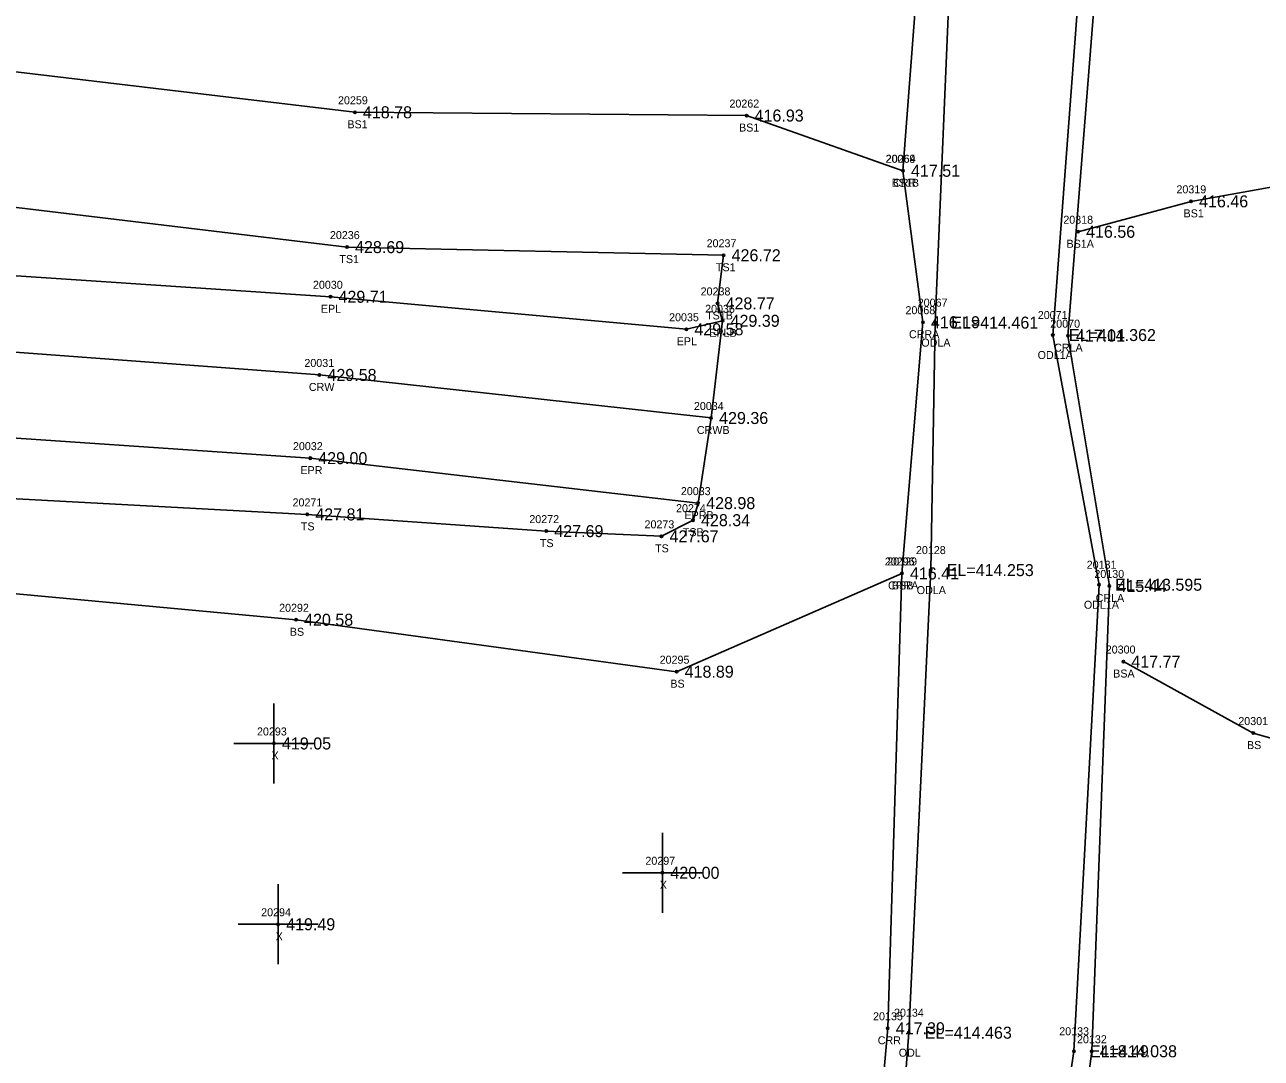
# Model space of a CAD drawing. Extents: x 1613184 to 1614731, y 770859 to 771868.
# Drawn here: x 1613805.1 to 1613959.6, y 771266.5 to 771395.6 of the extents above; entities that cross this region are included whole.
import ezdxf

# ---------------------------------------------------------------- set-up
doc = ezdxf.new("R2010")
doc.units = 0
for name, color, linetype in [('RD_DTM_BkLn1', 7, 'Continuous'), ('RD_DTM_BkLn2', 7, 'Continuous'), ('RD_DTM_BkLn_txCode', 7, 'Continuous'), ('RD_EX_H2O', 7, 'Continuous'), ('RD_EX_H2O_txCode', 7, 'Continuous'), ('RD_EX_Misc', 7, 'Continuous'), ('RD_EX_Misc_txCode', 7, 'Continuous'), ('RD_EX_Road', 7, 'Continuous'), ('RD_EX_Road_txCode', 7, 'Continuous'), ('RD_EX_TX_H2O_ELEV', 7, 'Continuous'), ('RD_EX_TX_Misc_ELEV', 7, 'Continuous'), ('RD_EX_TX_Road_ELEV', 7, 'Continuous'), ('RD_HC_Survey_ELEV', 7, 'Continuous'), ('RD_HC_Survey_txCode', 7, 'Continuous'), ('RD_SMD_Locator', 7, 'Continuous')]:
    doc.layers.add(name, color=color, linetype=linetype)

msp = doc.modelspace()

# ---------------------------------------------------------------- linework, layer by layer
at = {"layer": 'RD_DTM_BkLn1'}
msp.add_lwpolyline([(1613193.64, 771319.41), (1613293.11, 771329.14), (1613392.46, 771338.5), (1613492.95, 771347.08), (1613542.61, 771350.97), (1613592.52, 771354.09), (1613642.63, 771355.86), (1613692.27, 771356.69), (1613742.08, 771356.79), (1613792.13, 771355.6), (1613841.94, 771351.86), (1613890.87, 771346.48)], dxfattribs=at)
at = {"layer": 'RD_DTM_BkLn2'}
for points in [[(1613191.9, 771337.48), (1613291.44, 771345.53), (1613389.08, 771355.5), (1613435.73, 771361.94), (1613448.05, 771379.9), (1613456.58, 771373.81), (1613489.82, 771379.95), (1613539.65, 771385.9), (1613590.16, 771390.66), (1613642.18, 771393.2), (1613691.23, 771395.53), (1613743.12, 771392.35), (1613794.87, 771390.82), (1613846.37, 771384.69), (1613895.3, 771384.28), (1613914.84, 771377.38)], [(1613936.71, 771369.76), (1613950.83, 771373.56), (1613963.82, 771375.88), (1614069.43, 771354.05), (1614168.59, 771333.61), (1614242.69, 771319.53), (1614249.02, 771318.73)], [(1613192.28, 771333.37), (1613291.74, 771342.64), (1613389.11, 771353.66), (1613436.85, 771356.33), (1613492.16, 771363.71), (1613540.47, 771367.11), (1613591.24, 771372.7), (1613642.11, 771373.16), (1613691.12, 771373.65), (1613744.36, 771374.73), (1613793.64, 771374.02), (1613845.39, 771367.84), (1613892.43, 771366.82), (1613891.67, 771360.8)], [(1613888.61, 771333.71), (1613889.25, 771335.84), (1613890.87, 771346.48), (1613892.3, 771358.63), (1613891.67, 771360.8)], [(1613513, 771333.25), (1613544.25, 771334.4), (1613593.37, 771335.17), (1613642.92, 771335.51), (1613693.05, 771337.53), (1613742.72, 771338.4), (1613791.72, 771337.06), (1613840.42, 771334.43), (1613870.28, 771332.34), (1613884.67, 771331.69), (1613888.61, 771333.71)], [(1613531.71, 771317.92), (1613595.86, 771321.39), (1613644.57, 771324.66), (1613693.19, 771325.79), (1613742.08, 771324.98), (1613790.16, 771325.78), (1613839.02, 771321.26), (1613886.56, 771314.77), (1613914.71, 771327.05)], [(1613942.37, 771316.04), (1613958.6, 771307.1), (1613993.85, 771297.11), (1614061.98, 771289.14), (1614161.12, 771278.24), (1614255.97, 771263.05), (1614304.44, 771258.76), (1614327.58, 771260.25), (1614357.86, 771257.94), (1614459.3, 771244.57), (1614558.63, 771228.44), (1614632.25, 771215.15), (1614636.04, 771209.87), (1614639.16, 771208.8), (1614642.36, 771211.01), (1614643.75, 771203.68), (1614650.35, 771198.32), (1614658.52, 771198.65)]]:
    msp.add_lwpolyline(points, dxfattribs=at)
at = {"layer": 'RD_EX_H2O'}
for p, q in [((1613917.33, 771358.45), (1613914.71, 771327.05)), ((1613918.3, 771327.47), (1613918.86, 771358.4)), ((1613933.56, 771356.85), (1613939.34, 771325.64)), ((1613940.63, 771325.49), (1613935.44, 771356.77))]:
    msp.add_line(p, q, dxfattribs=at)
for points in [[(1613935.44, 771356.77), (1613943.27, 771455.38), (1613930.01, 771555.13), (1613904.31, 771653.52), (1613890.61, 771671.71), (1613879.59, 771707.51), (1613867.74, 771752.9), (1613852.65, 771773.53), (1613849.08, 771793.99), (1613835.96, 771848.52)], [(1613933.56, 771356.85), (1613941.09, 771457.11), (1613927.24, 771554.95), (1613896.69, 771649.06), (1613889.05, 771670.7), (1613877.65, 771707.88), (1613864.46, 771751.42), (1613851.59, 771772.54), (1613846.49, 771794.39), (1613833.03, 771846.8)], [(1613917.33, 771358.45), (1613914.84, 771377.38), (1613920.97, 771458.1), (1613902.34, 771553.43), (1613877.06, 771642.7), (1613869.36, 771660.93), (1613852.51, 771699.26), (1613841.87, 771743.26), (1613831.92, 771763.8), (1613826.06, 771789.11), (1613812.2, 771844.94)], [(1613918.86, 771358.4), (1613923.07, 771457.63), (1613904.68, 771553.56), (1613879.07, 771643.9), (1613870.63, 771662.43), (1613861.21, 771701.73), (1613845.61, 771745.37), (1613835.05, 771764.94), (1613829.4, 771789.26), (1613813.84, 771845.46)], [(1613914.71, 771327.05), (1613912.94, 771270.2), (1613909.29, 771229.14), (1613936.32, 771173.24), (1613961.59, 771155.78), (1613976.99, 771153.11), (1613987.89, 771138.66), (1614016.07, 771061.15), (1614064.07, 770971.34), (1614114.62, 770881.02)], [(1613918.3, 771327.47), (1613915.56, 771269.65), (1613912.54, 771229.9), (1613937.35, 771175.56), (1613962.55, 771156.92), (1613978.15, 771155.33), (1613989.65, 771139.95), (1614019.92, 771062.64), (1614066.64, 770972.38), (1614116.22, 770882.03)], [(1613939.34, 771325.64), (1613936.19, 771267.33), (1613931.54, 771235.48), (1613951.01, 771188.77), (1613971.87, 771179.88), (1613985.53, 771176.18), (1614010.21, 771154.12), (1614036.29, 771069.78), (1614094.78, 770976.9), (1614137.18, 770892.4)], [(1613940.63, 771325.49), (1613938.42, 771267.33), (1613934.3, 771235.92), (1613956.7, 771194.52), (1613973.34, 771185.91), (1613987.6, 771179.19), (1614011.07, 771155.33), (1614038.76, 771071.93), (1614097.41, 770977.46), (1614139.24, 770893.98)]]:
    msp.add_lwpolyline(points, dxfattribs=at)
at = {"layer": 'RD_EX_Misc'}
for p, q in [((1613836.26, 771300.8), (1613836.26, 771310.8)), ((1613831.26, 771305.8), (1613841.26, 771305.8)), ((1613884.78, 771284.64), (1613884.78, 771294.64)), ((1613879.78, 771289.64), (1613889.78, 771289.64)), ((1613836.78, 771278.2), (1613836.78, 771288.2)), ((1613831.78, 771283.2), (1613841.78, 771283.2))]:
    msp.add_line(p, q, dxfattribs=at)
at = {"layer": 'RD_EX_Road'}
for points in [[(1613192.48, 771329.15), (1613292.05, 771338.23), (1613391, 771348.45), (1613492.61, 771357.17), (1613541.86, 771361.21), (1613591.56, 771364.71), (1613642.92, 771366.4), (1613692.81, 771367.35), (1613742.66, 771367.02), (1613792.19, 771365.04), (1613843.32, 771361.63), (1613887.78, 771357.57), (1613892.3, 771358.63)], [(1613194.6, 771309.27), (1613294.55, 771318.15), (1613393.75, 771328.31), (1613493.74, 771336.74), (1613544.27, 771340.57), (1613593.48, 771343.76), (1613642.77, 771345.54), (1613692.58, 771346.11), (1613741.71, 771345.82), (1613791.79, 771344.79), (1613840.79, 771341.46), (1613889.25, 771335.84)]]:
    msp.add_lwpolyline(points, dxfattribs=at)
at = {"layer": 'RD_SMD_Locator'}
for centre in [(1613846.37, 771384.69), (1613895.3, 771384.28), (1613914.84, 771377.38), (1613914.84, 771377.38), (1613950.83, 771373.56), (1613936.71, 771369.76), (1613845.39, 771367.84), (1613892.43, 771366.82), (1613843.32, 771361.63), (1613891.67, 771360.8), (1613892.3, 771358.63), (1613917.33, 771358.45), (1613918.86, 771358.4), (1613887.78, 771357.57), (1613933.56, 771356.85), (1613935.44, 771356.77), (1613841.94, 771351.86), (1613890.87, 771346.48), (1613840.79, 771341.46), (1613889.25, 771335.84), (1613840.42, 771334.43), (1613888.61, 771333.71), (1613870.28, 771332.34), (1613884.67, 771331.69), (1613914.71, 771327.05), (1613914.71, 771327.05), (1613918.3, 771327.47), (1613939.34, 771325.64), (1613940.63, 771325.49), (1613839.02, 771321.26), (1613942.37, 771316.04), (1613886.56, 771314.77), (1613958.6, 771307.1), (1613836.26, 771305.8), (1613884.78, 771289.64), (1613836.78, 771283.2), (1613912.94, 771270.2), (1613915.56, 771269.65), (1613936.19, 771267.33), (1613938.42, 771267.33)]:
    msp.add_circle(centre, 0.15, dxfattribs=at)

# ---------------------------------------------------------------- texts
at = {"layer": 'RD_DTM_BkLn_txCode'}
for s, p in [('20259', (1613844.26, 771385.69)), ('20262', (1613893.16, 771385.28)), ('BS1', (1613845.43, 771382.69)), ('BS1', (1613894.36, 771382.28)), ('20264', (1613912.7, 771378.38)), ('BS1B', (1613913.42, 771375.38)), ('20319', (1613949, 771374.56)), ('20318', (1613934.87, 771370.76)), ('BS1', (1613949.89, 771371.56)), ('20236', (1613843.25, 771368.84)), ('20237', (1613890.31, 771367.82)), ('BS1A', (1613935.27, 771367.76)), ('TS1', (1613844.43, 771365.84)), ('TS1', (1613891.47, 771364.82)), ('20238', (1613889.56, 771361.8)), ('TS1B', (1613890.24, 771358.8)), ('20271', (1613838.58, 771335.43)), ('20274', (1613886.49, 771334.71)), ('TS', (1613839.62, 771332.43)), ('20272', (1613868.16, 771333.34)), ('20273', (1613882.55, 771332.69)), ('TSB', (1613887.34, 771331.71)), ('TS', (1613869.48, 771330.34)), ('TS', (1613883.87, 771329.69)), ('20296', (1613912.57, 771328.05)), ('BSB', (1613913.46, 771325.05)), ('20292', (1613836.9, 771322.26)), ('BS', (1613838.24, 771319.26)), ('20300', (1613940.17, 771317.04)), ('20295', (1613884.44, 771315.77)), ('BSA', (1613941.1, 771314.04)), ('BS', (1613885.78, 771312.77)), ('20301', (1613956.73, 771308.1)), ('BS', (1613957.82, 771305.1))]:
    msp.add_text(s, height=1, dxfattribs=at).set_placement(p)
at = {"layer": 'RD_EX_H2O_txCode'}
for s, p in [('20069', (1613912.66, 771378.38)), ('CRR', (1613913.59, 771375.38)), ('20067', (1613916.68, 771360.4)), ('20068', (1613915.15, 771359.45)), ('20071', (1613931.68, 771358.85)), ('20070', (1613933.24, 771357.77)), ('CRRA', (1613915.59, 771356.45)), ('ODLA', (1613917.13, 771355.4)), ('ODL1A', (1613931.66, 771353.85)), ('CRLA', (1613933.72, 771354.77)), ('20128', (1613916.46, 771329.47)), ('20129', (1613912.88, 771328.05)), ('20131', (1613937.79, 771327.64)), ('20130', (1613938.75, 771326.49)), ('CRRA', (1613912.97, 771325.05)), ('ODLA', (1613916.56, 771324.47)), ('CRLA', (1613938.91, 771323.49)), ('ODL1A', (1613937.44, 771322.64)), ('20135', (1613911.1, 771271.2)), ('20134', (1613913.72, 771271.65)), ('20133', (1613934.36, 771269.33)), ('CRR', (1613911.69, 771268.2)), ('20132', (1613936.58, 771268.33)), ('ODL', (1613914.31, 771266.65))]:
    msp.add_text(s, height=1, dxfattribs=at).set_placement(p)
at = {"layer": 'RD_EX_Misc_txCode'}
for s, p in [('20293', (1613834.14, 771306.8)), ('X', (1613835.95, 771303.8)), ('20297', (1613882.66, 771290.64)), ('X', (1613884.46, 771287.64)), ('20294', (1613834.66, 771284.2)), ('X', (1613836.47, 771281.2))]:
    msp.add_text(s, height=1, dxfattribs=at).set_placement(p)
at = {"layer": 'RD_EX_Road_txCode'}
for s, p in [('20030', (1613841.13, 771362.63)), ('EPL', (1613842.12, 771359.63)), ('20035', (1613885.62, 771358.57)), ('20036', (1613890.12, 771359.63)), ('EPL', (1613886.57, 771355.57)), ('EPLB', (1613890.63, 771356.63)), ('20032', (1613838.63, 771342.46)), ('EPR', (1613839.56, 771339.46)), ('20033', (1613887.09, 771336.84)), ('EPRB', (1613887.54, 771333.84))]:
    msp.add_text(s, height=1, dxfattribs=at).set_placement(p)
at = {"layer": 'RD_EX_TX_H2O_ELEV'}
for s, p in [('417.51', (1613915.84, 771376.63)), ('416.19', (1613918.33, 771357.7)), ('EL=414.461', (1613920.86, 771357.65)), ('EL=414.362', (1613935.56, 771356.1)), ('417.01', (1613936.44, 771356.02)), ('416.41', (1613915.71, 771326.3)), ('EL=414.253', (1613920.3, 771326.72)), ('EL=413.595', (1613941.34, 771324.89)), ('415.44', (1613941.63, 771324.74)), ('417.39', (1613913.94, 771269.45)), ('EL=414.463', (1613917.56, 771268.9)), ('EL=414.038', (1613938.19, 771266.58)), ('418.49', (1613939.42, 771266.58))]:
    msp.add_text(s, height=1.5, dxfattribs=at).set_placement(p)
at = {"layer": 'RD_EX_TX_Misc_ELEV'}
for s, p in [('418.78', (1613847.37, 771383.94)), ('416.93', (1613896.3, 771383.53)), ('417.51', (1613915.84, 771376.63)), ('416.46', (1613951.83, 771372.81)), ('416.56', (1613937.71, 771369.01)), ('428.69', (1613846.39, 771367.09)), ('426.72', (1613893.43, 771366.07)), ('428.77', (1613892.67, 771360.05)), ('427.81', (1613841.42, 771333.68)), ('428.34', (1613889.61, 771332.96)), ('427.69', (1613871.28, 771331.59)), ('427.67', (1613885.67, 771330.94)), ('416.41', (1613915.71, 771326.3)), ('420.58', (1613840.02, 771320.51)), ('417.77', (1613943.37, 771315.29)), ('418.89', (1613887.56, 771314.02)), ('419.05', (1613837.26, 771305.05)), ('420.00', (1613885.78, 771288.89)), ('419.49', (1613837.78, 771282.45))]:
    msp.add_text(s, height=1.5, dxfattribs=at).set_placement(p)
at = {"layer": 'RD_EX_TX_Road_ELEV'}
for s, p in [('429.71', (1613844.32, 771360.88)), ('429.39', (1613893.3, 771357.88)), ('429.58', (1613888.78, 771356.82)), ('429.00', (1613841.79, 771340.71)), ('428.98', (1613890.25, 771335.09))]:
    msp.add_text(s, height=1.5, dxfattribs=at).set_placement(p)
at = {"layer": 'RD_HC_Survey_ELEV'}
for s, p in [('429.58', (1613842.94, 771351.11)), ('429.36', (1613891.87, 771345.73))]:
    msp.add_text(s, height=1.5, dxfattribs=at).set_placement(p)
at = {"layer": 'RD_HC_Survey_txCode'}
for s, p in [('20031', (1613840.06, 771352.86)), ('CRW', (1613840.62, 771349.86)), ('20034', (1613888.72, 771347.48)), ('CRWB', (1613889.09, 771344.48))]:
    msp.add_text(s, height=1, dxfattribs=at).set_placement(p)

doc.saveas('drawing.dxf')
